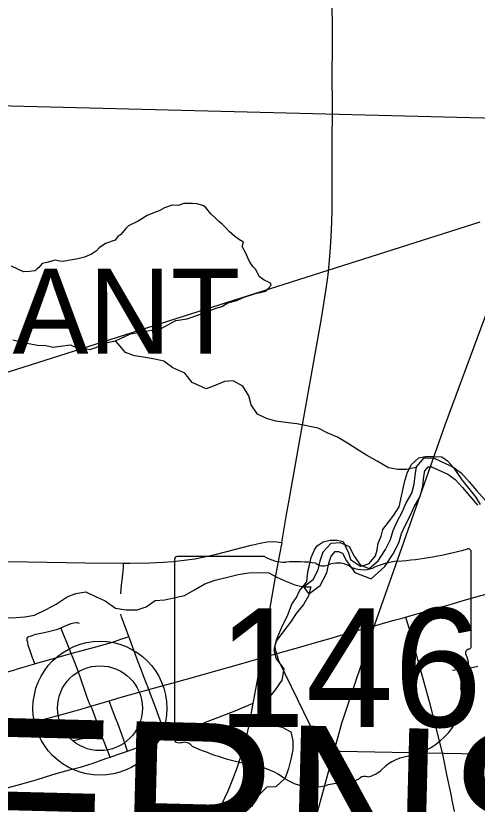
# Model space of a CAD drawing. Extents: x 0 to 34, y 0 to 22.
# Drawn here: x 5.999 to 6.512, y 20.326 to 21.203 of the extents above; entities that cross this region are included whole.
import ezdxf

# ---------------------------------------------------------------- set-up
doc = ezdxf.new("R2010")
doc.units = 0
for name, color, linetype in [('GM_X_City_Street', 7, 'Continuous'), ('GM_X_Corporation', 7, 'Continuous'), ('GM_X_Corporation_Text', 7, 'Continuous'), ('GM_X_County_Text', 7, 'Continuous'), ('GM_X_Major_River', 7, 'Continuous'), ('GM_X_Minor_Lake', 7, 'Continuous'), ('GM_X_Minor_River', 7, 'Continuous'), ('GM_X_Rail_Line', 7, 'Continuous'), ('GM_X_State_Location', 7, 'Continuous'), ('GM_X_State_Route', 7, 'Continuous'), ('GM_X_State_Shield', 7, 'Continuous'), ('GM_X_Township_Road', 7, 'Continuous'), ('GM_X_Unincorporated', 7, 'Continuous'), ('GM_X_Unincorporated_Location', 7, 'Continuous')]:
    doc.layers.add(name, color=color, linetype=linetype)

msp = doc.modelspace()

# ---------------------------------------------------------------- linework, layer by layer
at = {"layer": 'GM_X_City_Street'}
for points in [[(6.43222, 20.53442), (6.45396, 20.54059), (6.47126, 20.54547), (6.482, 20.54851), (6.49512, 20.55235), (6.50943, 20.55647), (6.52138, 20.55983)], [(6.48458, 20.47547), (6.49008, 20.47598), (6.49704, 20.47687), (6.50448, 20.47801), (6.51256, 20.47969)]]:
    msp.add_lwpolyline(points, dxfattribs=at)
at = {"layer": 'GM_X_Corporation'}
msp.add_lwpolyline([(6.86066, 21.3734), (5.8536, 21.3734), (5.84726, 21.10616), (6.85437, 21.08062)], close=True, dxfattribs=at)
msp.add_lwpolyline([(6.93707, 20.374), (6.34053, 20.38528), (6.29151, 20.48558), (6.28911, 20.49295), (6.28791, 20.49779), (6.2873, 20.50283), (6.28875, 20.50912), (6.29164, 20.51549), (6.29561, 20.52486), (6.30101, 20.53568), (6.30605, 20.54865), (6.3111, 20.55622), (6.31435, 20.56343), (6.31975, 20.56991), (6.32264, 20.57352), (6.323, 20.57784), (6.32408, 20.58648), (6.32552, 20.5919), (6.32732, 20.60054), (6.33129, 20.6092), (6.33417, 20.61351), (6.34066, 20.61784), (6.34859, 20.62001), (6.35616, 20.62001), (6.36301, 20.6182), (6.36877, 20.60559), (6.3713, 20.59838), (6.38211, 20.59081), (6.38679, 20.59189), (6.39184, 20.59405), (6.39905, 20.60234), (6.40085, 20.60919), (6.40193, 20.6164), (6.40517, 20.62433), (6.40697, 20.63153), (6.41344, 20.63971), (6.41935, 20.64758), (6.42526, 20.65676), (6.42788, 20.66857), (6.43116, 20.68432), (6.43444, 20.69547), (6.43904, 20.704), (6.44692, 20.71122), (6.4561, 20.71319), (6.4725, 20.71253), (6.47907, 20.70794), (6.48563, 20.70072), (6.49481, 20.68694), (6.5099, 20.66792), (6.51515, 20.65938)], dxfattribs=at)
at = {"layer": 'GM_X_Major_River'}
msp.add_line((6.31888, 20.5681), (6.32473, 20.5602), dxfattribs=at)
for points in [[(6.31888, 20.5681), (6.32977, 20.57617), (6.33535, 20.58684), (6.33753, 20.59671), (6.34084, 20.60698), (6.34946, 20.61654), (6.35966, 20.6174), (6.36952, 20.61296), (6.37529, 20.60203), (6.38218, 20.59188), (6.39204, 20.58819), (6.40179, 20.59701), (6.41, 20.6096), (6.41557, 20.62064), (6.41851, 20.63052), (6.42296, 20.64042), (6.42854, 20.65109), (6.43299, 20.66136), (6.43932, 20.67204), (6.44188, 20.68192), (6.44293, 20.69178), (6.44436, 20.70127), (6.45297, 20.71121), (6.46317, 20.71132), (6.47266, 20.70687), (6.48405, 20.70168), (6.49394, 20.69459), (6.50309, 20.68483), (6.51112, 20.67507), (6.52066, 20.66418)], [(6.32473, 20.5602), (6.33744, 20.56962), (6.34467, 20.58344), (6.34703, 20.59413), (6.34956, 20.60196), (6.35416, 20.60707), (6.35794, 20.60739), (6.36241, 20.60538), (6.36685, 20.59696), (6.3758, 20.58377), (6.3942, 20.57689), (6.40933, 20.59057), (6.41853, 20.60468), (6.42475, 20.617), (6.42775, 20.62709), (6.43181, 20.63613), (6.43742, 20.64685), (6.44176, 20.65689), (6.44849, 20.66822), (6.45158, 20.68016), (6.45268, 20.69053), (6.45365, 20.69698), (6.4575, 20.70143), (6.46103, 20.70146), (6.46854, 20.69795), (6.4791, 20.69314), (6.48742, 20.68716), (6.4957, 20.67834), (6.50362, 20.66871), (6.51237, 20.65873)], [(6.32473, 20.5602), (6.33744, 20.56962), (6.34467, 20.58344), (6.34703, 20.59413), (6.34956, 20.60196), (6.35416, 20.60707), (6.35794, 20.60739), (6.36241, 20.60538), (6.36685, 20.59696), (6.3758, 20.58377), (6.3942, 20.57689), (6.40933, 20.59057), (6.41853, 20.60468), (6.42475, 20.617), (6.42775, 20.62709), (6.43181, 20.63613), (6.43742, 20.64685), (6.44176, 20.65689), (6.44849, 20.66822), (6.45158, 20.68016), (6.45268, 20.69053), (6.45365, 20.69698), (6.4575, 20.70143), (6.46103, 20.70146), (6.46854, 20.69795), (6.4791, 20.69314), (6.48742, 20.68716), (6.4957, 20.67834), (6.50362, 20.66871), (6.51237, 20.65873)]]:
    msp.add_lwpolyline(points, dxfattribs=at)
at = {"layer": 'GM_X_Minor_Lake'}
for points in [[(6.20025, 20.99385), (6.19533, 20.99417), (6.18588, 20.99407), (6.17947, 20.99173), (6.17305, 20.99204), (6.16437, 20.9893), (6.15836, 20.98583), (6.15157, 20.98348), (6.14517, 20.98076), (6.13502, 20.97459), (6.12448, 20.96918), (6.12148, 20.96611), (6.11587, 20.95961), (6.11249, 20.95731), (6.1095, 20.95349), (6.09894, 20.94958), (6.0918, 20.94496), (6.08881, 20.94152), (6.08317, 20.93767), (6.07564, 20.93456), (6.0681, 20.93259), (6.05564, 20.93018), (6.05187, 20.92977), (6.04808, 20.93011), (6.04278, 20.93118), (6.03373, 20.92844), (6.02845, 20.92725), (6.02471, 20.92304), (6.02246, 20.92112), (6.02058, 20.91921), (6.01454, 20.91838), (6.00812, 20.91794), (6.00357, 20.91978), (6.00129, 20.9209), (5.99446, 20.92423)], [(6.1101, 20.84134), (6.12666, 20.84909), (6.16063, 20.85513), (6.17719, 20.86402), (6.18965, 20.86605), (6.20208, 20.87035), (6.21037, 20.87346), (6.22167, 20.87775), (6.22808, 20.87971), (6.23485, 20.88357), (6.24466, 20.88633), (6.25181, 20.88944), (6.26538, 20.89413), (6.27708, 20.89652), (6.28307, 20.90341), (6.28229, 20.90567), (6.28001, 20.90679), (6.27508, 20.90901), (6.26976, 20.91274), (6.26591, 20.92065), (6.26247, 20.92403), (6.25902, 20.92968), (6.25709, 20.93382), (6.25478, 20.93872), (6.25056, 20.94626), (6.25203, 20.9512), (6.24785, 20.95381), (6.24214, 20.95791), (6.23643, 20.96278), (6.23299, 20.96653), (6.22842, 20.97103), (6.22461, 20.9744), (6.22118, 20.97777), (6.21584, 20.98264), (6.21011, 20.99016), (6.20707, 20.99202), (6.20025, 20.99385)], [(5.99593, 20.84241), (6.00312, 20.84059), (6.01562, 20.83807), (6.02319, 20.83663), (6.03265, 20.83636), (6.0406, 20.83454), (6.04853, 20.83539), (6.05986, 20.83702), (6.06707, 20.83369), (6.07463, 20.83339), (6.08145, 20.83195), (6.08937, 20.8343), (6.09351, 20.83662), (6.10066, 20.83973), (6.1101, 20.84134)]]:
    msp.add_lwpolyline(points, dxfattribs=at)
at = {"layer": 'GM_X_Minor_River'}
for points in [[(6.44424, 20.70048), (6.43342, 20.6985), (6.42359, 20.69839), (6.41337, 20.70018), (6.40083, 20.70763), (6.38905, 20.71432), (6.37803, 20.72103), (6.36776, 20.72774), (6.35674, 20.73444), (6.34536, 20.73925), (6.33511, 20.74444), (6.31163, 20.74912), (6.30179, 20.75016), (6.28817, 20.75229), (6.27794, 20.75521), (6.26769, 20.76003), (6.26079, 20.77018), (6.25806, 20.78039), (6.25154, 20.79093), (6.2409, 20.79688), (6.23108, 20.79639), (6.22129, 20.79212), (6.21074, 20.78822), (6.19518, 20.79526), (6.18715, 20.8054), (6.17387, 20.81132), (6.16359, 20.81879), (6.15375, 20.82096), (6.14315, 20.82275), (6.13103, 20.82489), (6.12117, 20.82857), (6.11239, 20.83833), (6.1101, 20.84134)], [(5.9888, 20.53355), (5.99937, 20.53404), (6.0092, 20.53452), (6.02014, 20.53653), (6.03294, 20.54273), (6.04423, 20.54853), (6.05625, 20.55699), (6.06605, 20.5605), (6.077, 20.56252), (6.08839, 20.55695), (6.09863, 20.55251), (6.11005, 20.5443), (6.12178, 20.54253), (6.13388, 20.54228), (6.14405, 20.5458), (6.1542, 20.55272), (6.16478, 20.55359), (6.17496, 20.55559), (6.18666, 20.55837), (6.19794, 20.56455), (6.20923, 20.57149), (6.22091, 20.5754), (6.23449, 20.57858), (6.24618, 20.58173), (6.25826, 20.58337), (6.26922, 20.58387), (6.28019, 20.5836), (6.29006, 20.5784), (6.29993, 20.57396), (6.30941, 20.57027), (6.31888, 20.5681), (6.3272, 20.56781)], [(6.3272, 20.56781), (6.32426, 20.55793), (6.31905, 20.5484), (6.31082, 20.53846), (6.30448, 20.52854), (6.29701, 20.519), (6.28841, 20.50754), (6.28585, 20.49804), (6.28858, 20.48784), (6.29699, 20.47694), (6.29484, 20.46441), (6.28737, 20.45335), (6.27802, 20.44188), (6.27394, 20.43237), (6.27139, 20.42249), (6.28431, 20.41429), (6.29529, 20.41214), (6.30479, 20.40693), (6.30714, 20.39673), (6.30685, 20.38687), (6.30468, 20.37624), (6.30212, 20.36599), (6.29843, 20.35534), (6.28831, 20.34576), (6.27811, 20.34528), (6.26649, 20.33379), (6.26129, 20.3235)]]:
    msp.add_lwpolyline(points, dxfattribs=at)
at = {"layer": 'GM_X_Rail_Line'}
for points in [[(6.29112, 20.07945), (6.31716, 20.22143), (6.33256, 20.31076), (6.3613, 20.41652), (6.39855, 20.52738), (6.47628, 20.74816), (6.56447, 20.9858)], [(6.51481, 20.97324), (5.95873, 20.79674), (5.86586, 20.76789), (5.03113, 20.55115), (4.58492, 20.43545), (4.34941, 20.37459), (4.31137, 20.36496), (4.27289, 20.35244), (4.23108, 20.3354), (4.20683, 20.32133), (4.17885, 20.30398), (4.04289, 20.19451)]]:
    msp.add_lwpolyline(points, dxfattribs=at)
at = {"layer": 'GM_X_State_Route'}
msp.add_line((6.27219, 20.48895), (6.28806, 20.49353), dxfattribs=at)
for points in [[(6.31897, 20.75416), (6.31932, 20.75612), (6.32868, 20.80809), (6.33871, 20.86626), (6.34414, 20.89936), (6.34622, 20.91472), (6.34792, 20.93075), (6.34904, 20.94498), (6.34998, 20.96419), (6.35062, 20.98591), (6.35082, 21.00951), (6.3509, 21.05361), (6.35095, 21.10579), (6.35091, 21.13314), (6.35105, 21.17227), (6.351, 21.19152), (6.35083, 21.21386), (6.35088, 21.2281)], [(6.29478, 20.61726), (6.3001, 20.64823), (6.30288, 20.66438), (6.31259, 20.71882), (6.31897, 20.75416)], [(6.22235, 20.60418), (6.26085, 20.61417), (6.27057, 20.6164), (6.27857, 20.61782), (6.28625, 20.6182), (6.29478, 20.61726)], [(6.29478, 20.61726), (6.29225, 20.60374), (6.28683, 20.57474), (6.28226, 20.54911)], [(5.93754, 20.59703), (6.01209, 20.5956), (6.07671, 20.59479), (6.11901, 20.59436), (6.12579, 20.59429), (6.14812, 20.59466), (6.16299, 20.59534), (6.17412, 20.59616), (6.18645, 20.59744), (6.19809, 20.59912), (6.20905, 20.60118), (6.22235, 20.60418)], [(6.28226, 20.54911), (6.2791, 20.53137), (6.27509, 20.50751), (6.27219, 20.48895)], [(6.4284, 20.53331), (6.43222, 20.53442), (6.43615, 20.52118), (6.44163, 20.50256), (6.44965, 20.47279), (6.45844, 20.44067), (6.47345, 20.38193)], [(6.28806, 20.49353), (6.31841, 20.50209), (6.33388, 20.50648), (6.34282, 20.50908), (6.34698, 20.51033), (6.36306, 20.51501), (6.37202, 20.51754), (6.38097, 20.52004), (6.38997, 20.52245), (6.39295, 20.5233), (6.40308, 20.52621), (6.40786, 20.52752), (6.41981, 20.53081), (6.4284, 20.53331)], [(6.22322, 20.31677), (6.23154, 20.33348), (6.23518, 20.34139), (6.24039, 20.35407), (6.24508, 20.36693), (6.24962, 20.38052), (6.2531, 20.39248), (6.25652, 20.40575), (6.25958, 20.41973), (6.26313, 20.43863), (6.26383, 20.44233), (6.26815, 20.46618), (6.26984, 20.47661), (6.27219, 20.48895)], [(6.47345, 20.38193), (6.4781, 20.35765), (6.48218, 20.33885), (6.48295, 20.33523), (6.48382, 20.33098), (6.48619, 20.31814)]]:
    msp.add_lwpolyline(points, dxfattribs=at)
at = {"layer": 'GM_X_State_Shield'}
for p, q in [((6.50528, 20.50205), (6.50528, 20.60674)), ((6.1757, 20.59834), (6.1757, 20.39822)), ((6.27546, 20.60178), (6.17894, 20.60178)), ((6.50525, 20.50208), (6.50528, 20.50205))]:
    msp.add_line(p, q, dxfattribs=at)
for centre, major_axis, start_param, end_param in [((6.38788, 20.87461), (0.34952, 0), 4.814394, 5.042369), ((6.50162, 20.60717), (0.00367, 0), 6.141152, 7.989035), ((6.17947, 20.59876), (0.00382, 0), 1.712693, 3.28349), ((6.29845, 20.62501), (0.03703, 0), 4.042523, 4.731795), ((6.31073, 20.48943), (0.13295, 0), 1.404758, 1.657858), ((6.43246, 20.54066), (0.07032, 0), 1.699011, 2.107814), ((6.34091, 20.5998), (0.01068, 0), 3.836095, 5.185415), ((6.3566, 20.57667), (0.02221, 0), 0.950623, 2.079405), ((6.38527, 20.6084), (0.02672, 0), 4.081561, 5.145723), ((6.50137, 20.50165), (0.00393, 0), 5.05454, 6.418171), ((6.50443, 20.49437), (0.00568, 0), 1.883978, 3.671073), ((6.46831, 20.48114), (0.03409, 0), 5.934695, 6.695948), ((6.51843, 20.45825), (0.0248, 0), 2.387724, 3.262537), ((6.40746, 20.44493), (0.08742, 0), 5.101752, 6.440018), ((6.17951, 20.39778), (0.00385, 0), 3.00124, 4.508301), ((6.18009, 20.41825), (0.0294, 0), 4.665946, 4.897461), ((6.18611, 20.38667), (0.0106, 0), 0.519207, 1.627899), ((6.31993, 20.56647), (0.2524, 0), 4.195997, 4.488961), ((6.44432, 20.34203), (0.04788, 0), 1.647645, 2.488434), ((6.24468, 20.30831), (0.07897, 0), 0.823519, 1.323587), ((6.38366, 20.37882), (0.02824, 0), 4.937069, 5.64225), ((6.33009, 20.38568), (0.05011, 0), 4.026481, 4.996735), ((6.36271, 20.37069), (0.0267, 0), 4.691044, 5.507374), ((6.38686, 20.35131), (0.00752, 0), 1.147584, 2.315152), ((6.35905, 20.31649), (0.04118, 0), 1.495662, 1.94098)]:
    msp.add_ellipse(centre, major_axis=major_axis, ratio=0.8, start_param=start_param, end_param=end_param, dxfattribs=at)
at = {"layer": 'GM_X_Township_Road'}
msp.add_line((6.08269, 20.4352), (6.10299, 20.44119), dxfattribs=at)
for points in [[(6.11588, 20.56016), (6.11628, 20.56564), (6.11678, 20.57023), (6.11732, 20.57448), (6.11788, 20.57938), (6.11835, 20.58491), (6.11873, 20.59034), (6.11901, 20.59436)], [(6.12479, 20.51268), (6.1227, 20.51877), (6.11765, 20.5316), (6.11669, 20.53453), (6.11591, 20.53772)], [(6.04922, 20.52243), (6.05034, 20.52286), (6.05263, 20.52375), (6.05767, 20.52624), (6.06057, 20.52735), (6.06359, 20.52804), (6.06669, 20.52827), (6.0675, 20.52819), (6.06852, 20.52802), (6.06966, 20.52753)], [(6.01198, 20.51104), (6.01251, 20.51191), (6.01313, 20.51241), (6.01375, 20.51274), (6.015, 20.51329), (6.02159, 20.51519), (6.02886, 20.51694), (6.03556, 20.51839), (6.04279, 20.52015), (6.04573, 20.52107), (6.04922, 20.52243)], [(6.0608, 20.49394), (6.05617, 20.50528), (6.05235, 20.51498), (6.05026, 20.51995), (6.04922, 20.52243)], [(6.02025, 20.48246), (6.01879, 20.48654), (6.01754, 20.49), (6.01501, 20.49689), (6.01467, 20.49799), (6.01413, 20.49965), (6.01306, 20.50308), (6.01242, 20.50597), (6.0121, 20.50715), (6.01181, 20.5085), (6.01169, 20.50928), (6.01169, 20.51015), (6.01198, 20.51104)], [(6.0608, 20.49394), (6.06603, 20.4954), (6.07138, 20.49684), (6.08392, 20.50004), (6.09884, 20.50426), (6.10774, 20.50699), (6.11717, 20.51006), (6.12067, 20.51127), (6.12479, 20.51268)], [(6.14702, 20.45381), (6.14574, 20.45721), (6.14486, 20.45947), (6.14049, 20.471), (6.13851, 20.47617), (6.13495, 20.4854), (6.1319, 20.49341), (6.13084, 20.49628), (6.12577, 20.50984), (6.12479, 20.51268)], [(6.02025, 20.48246), (6.02092, 20.48265), (6.03457, 20.48636), (6.05653, 20.49275), (6.0608, 20.49394)], [(6.08269, 20.4352), (6.08087, 20.43916), (6.07862, 20.44494), (6.0708, 20.46785), (6.06635, 20.4801), (6.06269, 20.4893), (6.0608, 20.49394)], [(5.96222, 20.46536), (5.97021, 20.46781), (5.97362, 20.46887), (5.97592, 20.46957), (5.97888, 20.47033), (5.98479, 20.47201), (5.99824, 20.47585), (6.00001, 20.47628), (6.0075, 20.47879), (6.02025, 20.48246)], [(6.14702, 20.45381), (6.1602, 20.45753), (6.19136, 20.46607), (6.22548, 20.47562), (6.24401, 20.48083), (6.27219, 20.48895)], [(6.10299, 20.44119), (6.11896, 20.4459), (6.14702, 20.45381)], [(6.16688, 20.40046), (6.16576, 20.40334), (6.16153, 20.4142), (6.1595, 20.41989), (6.15319, 20.4373), (6.15002, 20.44588), (6.14702, 20.45381)], [(6.11204, 20.41731), (6.11148, 20.41878), (6.10673, 20.43092), (6.1044, 20.43733), (6.10299, 20.44119)], [(6.16688, 20.40046), (6.17683, 20.40424), (6.18951, 20.40921), (6.20502, 20.41538), (6.21006, 20.41756), (6.23147, 20.42575), (6.24475, 20.43094), (6.24871, 20.43263), (6.25784, 20.43643), (6.26313, 20.43863)], [(5.96244, 20.40153), (5.9686, 20.40283), (5.9836, 20.40688), (6.00686, 20.41363), (6.02822, 20.42004), (6.04493, 20.42472), (6.0611, 20.42908), (6.07667, 20.43341), (6.08269, 20.4352)], [(6.09355, 20.40597), (6.09124, 20.41325), (6.08397, 20.43238), (6.08269, 20.4352)], [(6.12342, 20.38535), (6.12226, 20.3886), (6.11875, 20.39848), (6.11204, 20.41731)], [(6.06365, 20.39716), (6.06825, 20.39821), (6.07089, 20.39884), (6.07325, 20.39946), (6.08729, 20.40385), (6.09355, 20.40597)], [(6.10396, 20.3787), (6.09651, 20.39743), (6.09479, 20.40205), (6.09355, 20.40597)], [(6.12342, 20.38535), (6.1327, 20.38847), (6.1396, 20.39085), (6.15655, 20.39669), (6.16293, 20.39895), (6.16688, 20.40046)], [(6.10396, 20.3787), (6.11213, 20.38155), (6.12342, 20.38535)], [(5.96158, 20.34038), (5.96349, 20.34032), (5.9677, 20.34027), (5.9713, 20.34063), (5.97446, 20.34107), (5.97839, 20.34181), (5.98255, 20.3426), (5.98498, 20.34322), (5.98785, 20.34394), (5.99117, 20.34495), (6.00075, 20.34744), (6.01681, 20.35211), (6.02166, 20.35347), (6.03224, 20.35682), (6.04404, 20.36048), (6.05898, 20.36447), (6.07214, 20.36798), (6.08049, 20.37038), (6.08522, 20.37192), (6.09925, 20.37699), (6.10396, 20.3787)]]:
    msp.add_lwpolyline(points, dxfattribs=at)
at = {"layer": 'GM_X_Unincorporated'}
for radius in [0.0744, 0.04716]:
    msp.add_circle((6.09269, 20.43305), radius, dxfattribs=at)
at = {"layer": 'GM_X_Unincorporated_Location'}
msp.add_line((6.09269, 20.43305), (6.09269, 20.43305), dxfattribs=at)

# ---------------------------------------------------------------- texts
at = {"layer": 'GM_X_Corporation_Text'}
msp.add_text('PLEASANT', height=0.094697, rotation=0.00001, dxfattribs=at).set_placement((5.58724, 20.82711))
at = {"layer": 'GM_X_County_Text'}
msp.add_text('GUERNSEY COUNTY', height=0.1893939, rotation=358.54305, dxfattribs=at).set_placement((5.55921, 20.24364))
at = {"layer": 'GM_X_State_Location'}
for s, p in [('s', (6.33679, 20.48497)), ('r', (6.33678, 20.48497))]:
    msp.add_text(s, height=0.000189, dxfattribs=at).set_placement(p)
msp.add_text('146', height=0.000189, rotation=0.00001, dxfattribs=at).set_placement((6.26993, 20.47119))
at = {"layer": 'GM_X_State_Shield'}
msp.add_text('146', height=0.131836, dxfattribs=at).set_placement((6.22312, 20.41233))

doc.saveas('drawing.dxf')
